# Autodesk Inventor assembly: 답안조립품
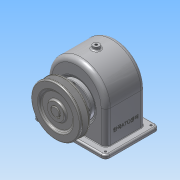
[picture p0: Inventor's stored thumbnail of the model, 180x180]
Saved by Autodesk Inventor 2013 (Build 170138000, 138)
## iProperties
Created: 2016-01
Part Number: 답안조립품
Document SubType Name: Assembly
Designer: Administrator
Author: Administrator
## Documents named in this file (15)
- C:\Users\Administrator\Desktop\시험\답안조립품.iam
- C:\Users\Administrator\Desktop\시험\본체.ipt
- C:\Users\Administrator\Desktop\시험\베어링 6203.ipt
- C:\Users\Administrator\Desktop\시험\뒤커버.ipt
- C:\Users\Administrator\Desktop\시험\볼트 M3 x 8.ipt
- C:\Users\Administrator\Desktop\시험\앞커버.ipt
- C:\Users\Administrator\Desktop\시험\볼트 M3 x 10.ipt
- C:\Users\Administrator\Desktop\시험\오일씰 28 40 8.ipt
- C:\Users\Administrator\Desktop\시험\축.ipt
- C:\Users\Administrator\Desktop\시험\부시1.ipt
- C:\Users\Administrator\Desktop\시험\스퍼기어.ipt
- C:\Users\Administrator\Desktop\시험\키 - 6 x 6 x 22.ipt
- C:\Users\Administrator\Desktop\시험\키 - 5 x 5 x 18.ipt
- C:\Users\Administrator\Desktop\시험\V-벨트풀리.ipt
- C:\Users\Administrator\Desktop\시험\멈춤나사 - M4x10.ipt
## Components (9 placed, 3 different names)
1. V-벨트풀리:1 — 각도:2
2. ISO 4762 M3 x 8:1
3. ISO 4762 M3 x 8:2
4. ISO 4762 M3 x 8:3
5. ISO 4762 M3 x 8:4
6. ISO 4762 M3 x 10:1
7. ISO 4762 M3 x 10:2
8. ISO 4762 M3 x 10:3
9. ISO 4762 M3 x 10:4
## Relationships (1: Angle 1)
- 각도:2 [Angle]: V-벨트풀리:1
